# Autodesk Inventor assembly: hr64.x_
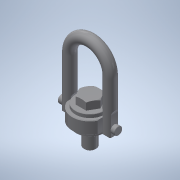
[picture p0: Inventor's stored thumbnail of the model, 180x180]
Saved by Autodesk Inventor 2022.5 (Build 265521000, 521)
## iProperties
Part Number: hr64.x_
Material: 一般
Document SubType Name: Assembly
Designer: ImaoCorp
Sending System: SOLIDWORKS 2017-2017317
MC: AMD64
MC_MODEL: Intel64 Family 6 Model 60 Stepping 3, GenuineIntel
OS: Windows_NT
FRU: Parasolid Version 29.0, build 201,  4-17-2017
FORMAT: text
GUISE: transmit
KEY: hr64
FILE: hr64.x_t
DATE: Mon Jul 01 17:38:41 2019
Author: ImaoCorp
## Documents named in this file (3)
- X:\14_SW2022-Inv2022\00_全2023-1023新製品(TCC)まで\h\hr64\HR64.iam
- X:\14_SW2022-Inv2022\00_全2023-1023新製品(TCC)まで\h\hr64\hr64_01.ipt
- X:\14_SW2022-Inv2022\00_全2023-1023新製品(TCC)まで\h\hr64\hr64_02.ipt
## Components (2 placed, 2 different names)
1. hr64_01
2. hr64_02
